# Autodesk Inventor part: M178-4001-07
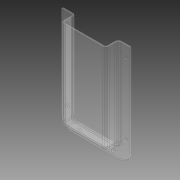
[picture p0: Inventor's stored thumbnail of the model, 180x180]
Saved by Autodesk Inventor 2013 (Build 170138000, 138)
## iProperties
Created: 2004-11
Part Number: M178-4001-07
Material: Plastic, Clear
Document SubType Name: Modeling
Designer: Autodesk, Inc.
Manufacturer: Standard
Standards Organization: Custom
Description: TOOL CADDY, PLASTIC, 2 x 4 x 0.75
Mass: 26.1813 g
Surface Area: 237.698 cm^2
Volume: 21.8178 cm^3
Density: 1.2 g/cm^3
CAGE: 1LJX3
Dept. ID: Product Design
Description #2: ---
Finish #1: ---
Finish #2: ---
Material ID: ---
Project Number: ---
Author: Autodesk, Inc.
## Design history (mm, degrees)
derived "M178-4001-XX.ipt"
body "Solid1"
tag "TaggingFeature2"
feature "Solid1::M178-4001-XX.ipt" dims "ScaleForDerivedMember" = 10
